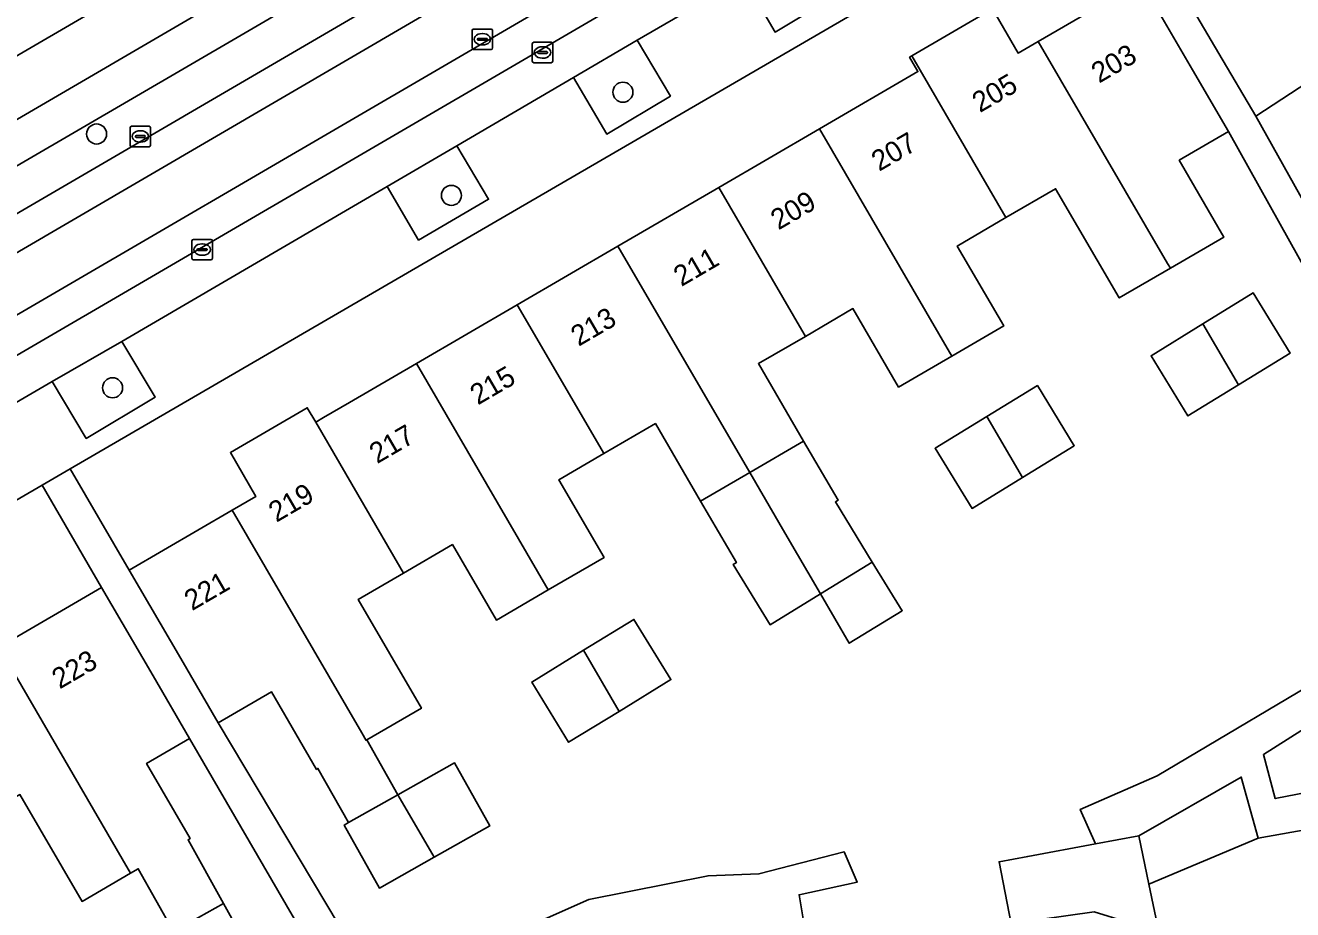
# Model space of a CAD drawing. Extents: x 158352 to 159489, y 383828 to 384603.
# Drawn here: x 158694.5 to 158756.3, y 384098.8 to 384142 of the extents above; entities that cross this region are included whole.
import ezdxf

# ---------------------------------------------------------------- set-up
doc = ezdxf.new("R2010")
doc.units = 0
for name, color, linetype in [('IMGEO_Boom', 7, 'Continuous'), ('IMGEO_Erf', 7, 'Continuous'), ('IMGEO_Groenvoorziening', 7, 'Continuous'), ('IMGEO_Kolk', 7, 'Continuous'), ('IMGEO_Pand', 7, 'Continuous'), ('IMGEO_Pand_nummerreeks', 7, 'Continuous'), ('IMGEO_Parkeervlak_open', 7, 'Continuous'), ('IMGEO_Rijbaan_lokaal_gesloten', 7, 'Continuous'), ('IMGEO_Rijbaan_lokaal_open', 7, 'Continuous'), ('IMGEO_Rioolput', 7, 'Continuous'), ('IMGEO_Voetpad_open', 7, 'Continuous')]:
    doc.layers.add(name, color=color, linetype=linetype)

msp = doc.modelspace()

# ---------------------------------------------------------------- linework, layer by layer
at = {"layer": 'IMGEO_Boom'}
for centre in [(158723.642, 384138.721), (158697.952, 384136.681), (158715.271, 384133.683), (158698.731, 384124.289)]:
    msp.add_circle(centre, 0.489, dxfattribs=at)
at = {"layer": 'IMGEO_Erf'}
for points in [[(158728.317, 384134.065), (158733.235, 384136.93), (158738.044, 384139.731), (158737.635, 384140.432), (158737.742, 384140.494), (158741.679, 384142.788), (158742.934, 384140.632), (158743.915, 384141.203), (158748.936, 384144.128), (158746.068, 384149.06), (158696.667, 384120.326), (158699.543, 384115.387), (158704.565, 384118.312), (158705.726, 384118.988), (158704.48, 384121.126), (158708.237, 384123.314), (158708.648, 384122.608), (158709.034, 384122.833), (158710.296, 384123.568), (158713.565, 384125.472), (158718.482, 384128.337), (158723.4, 384131.201)], [(158749.422, 384125.856), (158751.95, 384127.408), (158754.412, 384128.919), (158756.216, 384125.98), (158753.686, 384124.427), (158751.225, 384122.917)], [(158743.147, 384119.907), (158740.687, 384118.397), (158738.884, 384121.336), (158741.411, 384122.887), (158743.874, 384124.399), (158745.678, 384121.46)], [(158723.454, 384108.49), (158720.994, 384106.98), (158719.191, 384109.919), (158721.718, 384111.47), (158724.181, 384112.982), (158725.985, 384110.043)]]:
    msp.add_lwpolyline(points, close=True, dxfattribs=at)
for points in [[(158757.506, 384139.484), (158754.537, 384137.547), (158766.668, 384115.877)], [(158763.607, 384118.148), (158753.204, 384136.8), (158750.796, 384135.397), (158752.98, 384131.648), (158750.367, 384130.126), (158747.874, 384128.674), (158744.766, 384134.011), (158742.341, 384132.599), (158739.96, 384131.212), (158742.232, 384127.312), (158739.695, 384125.835), (158737.101, 384124.324), (158734.871, 384128.153), (158732.548, 384126.8), (158730.26, 384125.467), (158732.463, 384121.686), (158734.145, 384118.799), (158734.012, 384118.718), (158735.816, 384115.779), (158737.276, 384113.4), (158734.691, 384111.813), (158733.285, 384114.226), (158730.825, 384112.716), (158729.022, 384115.655), (158729.182, 384115.753), (158727.433, 384118.756), (158725.228, 384122.541), (158722.711, 384121.075), (158720.517, 384119.797), (158722.726, 384116.005), (158720.002, 384114.418), (158717.469, 384112.943), (158715.32, 384116.631), (158712.937, 384115.243), (158710.715, 384113.948), (158713.807, 384108.64), (158711.15, 384107.093), (158712.659, 384104.412), (158715.428, 384105.97), (158717.14, 384102.895), (158714.431, 384101.37), (158711.753, 384099.863), (158710.041, 384102.939), (158710.247, 384103.055), (158708.758, 384105.7), (158708.686, 384105.658), (158706.481, 384109.443), (158703.886, 384107.932), (158711.747, 384094.756), (158721.977, 384099.298), (158727.797, 384100.464), (158730.28, 384100.554), (158734.439, 384101.63), (158735.083, 384100.15), (158732.24, 384099.536), (158732.47, 384098.16)], [(158663.516, 384097.136), (158667.47, 384099.439), (158667.836, 384098.811), (158672.701, 384101.645), (158677.609, 384104.504), (158682.517, 384107.363), (158686.152, 384109.48), (158687.223, 384110.104), (158687.424, 384110.221), (158687.039, 384110.883), (158690.908, 384113.137), (158692.142, 384111.017), (158693.182, 384111.623), (158698.194, 384114.542), (158695.294, 384119.527), (158650.651, 384093.56)], [(158773.666, 384118.284), (158754.906, 384106.382), (158755.484, 384104.227), (158775.984, 384108.212)], [(158742.589, 384098.118), (158742.003, 384101.142), (158743.404, 384101.402), (158746.706, 384102.014), (158745.966, 384103.699), (158749.715, 384105.347), (158759.047, 384110.871)], [(158710.112, 384094.03), (158702.49, 384107.167), (158700.391, 384105.945), (158702.524, 384102.282), (158702.415, 384102.219), (158704.147, 384099.109), (158705.859, 384096.034)], [(158701.706, 384097.735), (158699.981, 384100.801), (158699.611, 384100.586), (158697.245, 384099.208), (158694.208, 384104.423), (158691.666, 384102.942), (158689.344, 384101.59), (158691.616, 384097.689)], [(158767.698, 384087.716), (158764.614, 384104.071), (158754.651, 384102.29), (158749.314, 384100.047), (158749.803, 384097.716)]]:
    msp.add_lwpolyline(points, dxfattribs=at)
at = {"layer": 'IMGEO_Groenvoorziening'}
for points in [[(158705.587, 384147.238), (158693.057, 384139.923), (158686.342, 384135.99), (158686.267, 384136.115), (158685.669, 384135.769), (158687.07, 384133.326), (158705.582, 384144.133), (158706.962, 384144.94), (158706.888, 384145.075), (158705.68, 384147.291)], [(158732.669, 384146.127), (158729.543, 384144.295), (158731.072, 384141.657), (158734.16, 384143.528)], [(158721.234, 384139.439), (158722.85, 384136.674), (158725.959, 384138.531), (158724.331, 384141.256)], [(158713.672, 384131.503), (158717.082, 384133.496), (158715.536, 384136.098), (158712.14, 384134.125)], [(158697.447, 384121.82), (158700.802, 384123.825), (158699.176, 384126.548), (158695.787, 384124.599)]]:
    msp.add_lwpolyline(points, close=True, dxfattribs=at)
at = {"layer": 'IMGEO_Kolk'}
for p, q in [((158719.218, 384140.236), (158719.218, 384141.088)), ((158719.293, 384141.162), (158720.145, 384141.162)), ((158719.477, 384140.656), (158719.477, 384140.668)), ((158719.915, 384140.619), (158719.517, 384140.619)), ((158719.52, 384140.705), (158719.918, 384140.705)), ((158719.706, 384140.942), (158719.731, 384140.942)), ((158719.961, 384140.668), (158719.961, 384140.656)), ((158720.219, 384141.088), (158720.219, 384140.236)), ((158720.145, 384140.162), (158719.293, 384140.162)), ((158719.729, 384140.382), (158719.704, 384140.382)), ((158699.586, 384136.135), (158699.586, 384136.987)), ((158699.661, 384137.061), (158700.513, 384137.061)), ((158700.587, 384136.987), (158700.587, 384136.135)), ((158699.845, 384136.555), (158699.845, 384136.567)), ((158700.283, 384136.518), (158699.885, 384136.518)), ((158699.888, 384136.604), (158700.286, 384136.604)), ((158700.097, 384136.281), (158700.072, 384136.281)), ((158700.074, 384136.841), (158700.099, 384136.841)), ((158700.329, 384136.567), (158700.329, 384136.555)), ((158700.513, 384136.061), (158699.661, 384136.061)), ((158702.604, 384130.611), (158702.604, 384131.463)), ((158702.679, 384131.537), (158703.531, 384131.537)), ((158703.092, 384131.317), (158703.117, 384131.317)), ((158703.605, 384131.463), (158703.605, 384130.611)), ((158702.863, 384131.031), (158702.863, 384131.043)), ((158703.301, 384130.994), (158702.903, 384130.994)), ((158702.906, 384131.08), (158703.304, 384131.08)), ((158703.115, 384130.757), (158703.09, 384130.757)), ((158703.347, 384131.043), (158703.347, 384131.031)), ((158703.531, 384130.537), (158702.679, 384130.537))]:
    msp.add_line(p, q, dxfattribs=at)
for points in [[(158719.218, 384140.236), (158719.218, 384141.088)], [(158719.293, 384141.162), (158720.145, 384141.162)], [(158720.219, 384141.088), (158720.219, 384140.236)], [(158720.145, 384140.162), (158719.293, 384140.162)], [(158699.586, 384136.135), (158699.586, 384136.987)], [(158699.661, 384137.061), (158700.513, 384137.061)], [(158700.587, 384136.987), (158700.587, 384136.135)], [(158700.513, 384136.061), (158699.661, 384136.061)], [(158702.604, 384130.611), (158702.604, 384131.463)], [(158702.679, 384131.537), (158703.531, 384131.537)], [(158703.605, 384131.463), (158703.605, 384130.611)], [(158703.531, 384130.537), (158702.679, 384130.537)]]:
    msp.add_lwpolyline(points, dxfattribs=at)
for centre, radius, start, end in [((158719.295, 384141.086), 0.0765, 91.55205, 178.44795), ((158719.295, 384141.086), 0.0765, 91.55205, 178.44795), ((158719.517, 384140.665), 0.0403, 85.87752, 175.75265), ((158719.514, 384140.655), 0.0366, 178.93798, 274.71019), ((158719.918, 384140.662), 0.043, 264.86636, 352.45326), ((158719.922, 384140.667), 0.0386, 1.73085, 96.63898), ((158720.143, 384141.086), 0.0765, 1.55205, 88.44795), ((158720.143, 384141.086), 0.0765, 1.55205, 88.44795), ((158719.295, 384140.238), 0.0765, 181.55205, 268.44795), ((158719.295, 384140.238), 0.0765, 181.55205, 268.44795), ((158720.143, 384140.238), 0.0765, 271.55205, 358.44795), ((158720.143, 384140.238), 0.0765, 271.55205, 358.44795), ((158699.663, 384136.985), 0.0765, 91.55205, 178.44795), ((158699.663, 384136.985), 0.0765, 91.55205, 178.44795), ((158700.511, 384136.985), 0.0765, 1.55205, 88.44795), ((158700.511, 384136.985), 0.0765, 1.55205, 88.44795), ((158699.885, 384136.564), 0.0403, 85.87752, 175.75265), ((158699.882, 384136.554), 0.0366, 178.93798, 274.71019), ((158700.286, 384136.561), 0.043, 264.86636, 352.45326), ((158700.29, 384136.566), 0.0386, 1.73085, 96.63898), ((158699.663, 384136.137), 0.0765, 181.55205, 268.44795), ((158699.663, 384136.137), 0.0765, 181.55205, 268.44795), ((158700.511, 384136.137), 0.0765, 271.55205, 358.44795), ((158700.511, 384136.137), 0.0765, 271.55205, 358.44795), ((158702.681, 384131.461), 0.0765, 91.55205, 178.44795), ((158702.681, 384131.461), 0.0765, 91.55205, 178.44795), ((158703.529, 384131.461), 0.0765, 1.55205, 88.44795), ((158703.529, 384131.461), 0.0765, 1.55205, 88.44795), ((158702.903, 384131.04), 0.0403, 85.87752, 175.75265), ((158702.9, 384131.03), 0.0366, 178.93798, 274.71019), ((158703.304, 384131.037), 0.043, 264.86636, 352.45326), ((158703.308, 384131.042), 0.0386, 1.73085, 96.63898), ((158702.681, 384130.613), 0.0765, 181.55205, 268.44795), ((158702.681, 384130.613), 0.0765, 181.55205, 268.44795), ((158703.529, 384130.613), 0.0765, 271.55205, 358.44795), ((158703.529, 384130.613), 0.0765, 271.55205, 358.44795)]:
    msp.add_arc(centre, radius, start, end, dxfattribs=at)
for centre, major_axis, ratio, start_param, end_param in [((158719.705, 384140.662), (-0.387, 0.002), 0.722429, 4.712389, 7.853982), ((158719.73, 384140.662), (-0.39, 0.002), 0.717154, 1.570796, 4.712389), ((158700.073, 384136.561), (-0.387, 0.002), 0.722429, 4.712389, 7.853982), ((158700.098, 384136.561), (-0.39, 0.002), 0.717154, 1.570796, 4.712389), ((158703.091, 384131.037), (-0.387, 0.002), 0.722429, 4.712389, 7.853982), ((158703.116, 384131.037), (-0.39, 0.002), 0.717154, 1.570796, 4.712389)]:
    msp.add_ellipse(centre, major_axis=major_axis, ratio=ratio, start_param=start_param, end_param=end_param, dxfattribs=at)
at = {"layer": 'IMGEO_Pand'}
msp.add_lwpolyline([(158653.864, 384149.026), (158667.797, 384125.161), (158676.397, 384130.204), (158676.31, 384130.355), (158672.899, 384136.248), (158683.572, 384142.468), (158689.645, 384146.008), (158692.983, 384140.276), (158692.881, 384140.213), (158693.057, 384139.923), (158705.587, 384147.238), (158703.871, 384150.068), (158727.441, 384163.801), (158727.604, 384163.526), (158727.921, 384163.713), (158725.073, 384168.559)], dxfattribs=at)
for points in [[(158762.253, 384137.116), (158762.181, 384137.223), (158754.924, 384148.07), (158750.204, 384144.913), (158752.739, 384140.604), (158754.537, 384137.547), (158757.506, 384139.484), (158760.068, 384135.654)], [(158743.915, 384141.203), (158750.233, 384130.355), (158750.367, 384130.126), (158752.98, 384131.648), (158750.796, 384135.397), (158753.204, 384136.8), (158751.452, 384139.808), (158748.936, 384144.128)], [(158743.915, 384141.203), (158742.934, 384140.632), (158741.679, 384142.788), (158737.742, 384140.494), (158742.341, 384132.599), (158744.766, 384134.011), (158747.874, 384128.674), (158750.367, 384130.126), (158750.233, 384130.355)], [(158733.235, 384136.93), (158739.695, 384125.835), (158742.232, 384127.312), (158739.96, 384131.212), (158742.341, 384132.599), (158737.742, 384140.494), (158737.635, 384140.432), (158738.044, 384139.731)], [(158733.235, 384136.93), (158728.317, 384134.065), (158732.484, 384126.91), (158732.548, 384126.8), (158734.871, 384128.153), (158737.101, 384124.324), (158739.695, 384125.835)], [(158729.833, 384120.154), (158732.463, 384121.686), (158730.26, 384125.467), (158732.548, 384126.8), (158732.484, 384126.91), (158728.317, 384134.065), (158723.4, 384131.201)], [(158718.482, 384128.337), (158722.622, 384121.228), (158722.711, 384121.075), (158725.228, 384122.541), (158727.433, 384118.756), (158729.833, 384120.154), (158723.4, 384131.201)], [(158753.686, 384124.427), (158756.216, 384125.98), (158754.412, 384128.919), (158751.95, 384127.408)], [(158718.482, 384128.337), (158713.565, 384125.472), (158720.002, 384114.418), (158722.726, 384116.005), (158720.517, 384119.797), (158722.711, 384121.075), (158722.622, 384121.228)], [(158753.686, 384124.427), (158751.95, 384127.408), (158749.422, 384125.856), (158751.225, 384122.917)], [(158713.565, 384125.472), (158710.296, 384123.568), (158709.034, 384122.833), (158708.648, 384122.608), (158712.756, 384115.553), (158712.937, 384115.243), (158715.32, 384116.631), (158717.469, 384112.943), (158720.002, 384114.418)], [(158743.147, 384119.907), (158745.678, 384121.46), (158743.874, 384124.399), (158741.411, 384122.887)], [(158712.937, 384115.243), (158712.756, 384115.553), (158708.648, 384122.608), (158708.237, 384123.314), (158704.48, 384121.126), (158705.726, 384118.988), (158704.565, 384118.312), (158710.892, 384107.447), (158711.111, 384107.07), (158711.15, 384107.093), (158713.807, 384108.64), (158710.715, 384113.948)], [(158743.147, 384119.907), (158741.411, 384122.887), (158738.884, 384121.336), (158740.687, 384118.397)], [(158734.012, 384118.718), (158734.145, 384118.799), (158732.463, 384121.686), (158729.833, 384120.154), (158731.549, 384117.206), (158733.285, 384114.226), (158735.816, 384115.779)], [(158731.549, 384117.206), (158729.833, 384120.154), (158727.433, 384118.756), (158729.182, 384115.753), (158729.022, 384115.655), (158730.825, 384112.716), (158733.285, 384114.226)], [(158704.565, 384118.312), (158699.543, 384115.387), (158702.06, 384111.067), (158703.886, 384107.932), (158706.481, 384109.443), (158708.686, 384105.658), (158708.758, 384105.7), (158710.247, 384103.055), (158712.659, 384104.412), (158711.15, 384107.093), (158711.111, 384107.07), (158710.892, 384107.447)], [(158735.816, 384115.779), (158733.285, 384114.226), (158734.691, 384111.813), (158737.276, 384113.4)], [(158700.711, 384110.222), (158698.194, 384114.542), (158693.182, 384111.623), (158699.611, 384100.586), (158699.981, 384100.801), (158701.706, 384097.735), (158704.147, 384099.109), (158702.415, 384102.219), (158702.524, 384102.282), (158700.391, 384105.945), (158702.49, 384107.167)], [(158693.182, 384111.623), (158692.142, 384111.017), (158690.908, 384113.137), (158687.039, 384110.883), (158687.424, 384110.221), (158691.597, 384103.06), (158691.666, 384102.942), (158694.208, 384104.423), (158697.245, 384099.208), (158699.611, 384100.586)], [(158721.718, 384111.47), (158723.454, 384108.49), (158725.985, 384110.043), (158724.181, 384112.982)], [(158721.718, 384111.47), (158719.191, 384109.919), (158720.994, 384106.98), (158723.454, 384108.49)], [(158714.431, 384101.37), (158717.14, 384102.895), (158715.428, 384105.97), (158712.659, 384104.412)], [(158748.819, 384102.406), (158749.314, 384100.047), (158754.651, 384102.29), (158753.83, 384105.283)], [(158712.659, 384104.412), (158710.247, 384103.055), (158710.041, 384102.939), (158711.753, 384099.863), (158714.431, 384101.37)], [(158748.819, 384102.406), (158746.706, 384102.014), (158743.404, 384101.402), (158742.003, 384101.142), (158742.589, 384098.118), (158743.219, 384098.209), (158743.987, 384098.32), (158746.652, 384098.705), (158749.803, 384097.716), (158749.314, 384100.047)], [(158704.147, 384099.109), (158701.706, 384097.735), (158701.379, 384097.551), (158703.151, 384094.509), (158705.859, 384096.034)]]:
    msp.add_lwpolyline(points, close=True, dxfattribs=at)
at = {"layer": 'IMGEO_Parkeervlak_open'}
for points in [[(158734.535, 384156.927), (158732.618, 384157.353), (158732.413, 384157.398), (158732.246, 384157.41), (158732.06, 384157.367), (158715.82, 384147.827), (158672.977, 384122.843), (158669.192, 384120.661), (158669.166, 384120.646)], [(158738.971, 384152.091), (158738.379, 384151.745), (158647.204, 384098.556)], [(158695.787, 384124.599), (158699.176, 384126.548), (158712.14, 384134.125), (158715.536, 384136.098), (158721.234, 384139.439), (158724.331, 384141.256), (158729.543, 384144.295), (158732.669, 384146.127), (158736.874, 384148.589)], [(158667.252, 384117.177), (158667.528, 384117.313), (158716.96, 384146.173)], [(158648.598, 384098.717), (158650.189, 384098.335), (158650.96, 384098.425), (158661.287, 384104.498), (158665.178, 384106.745), (158678.479, 384114.472), (158681.775, 384116.427), (158695.787, 384124.599)]]:
    msp.add_lwpolyline(points, dxfattribs=at)
at = {"layer": 'IMGEO_Rijbaan_lokaal_gesloten'}
for points in [[(158736.245, 384155.536), (158735.439, 384156.968), (158716.96, 384146.173), (158667.528, 384117.313), (158667.252, 384117.177), (158666.707, 384116.86), (158659.63, 384112.744), (158655.57, 384110.383), (158644.427, 384103.877), (158644.032, 384103.668), (158644.915, 384102.204)], [(158738.379, 384151.745), (158737.545, 384153.226), (158646.22, 384099.951), (158647.12, 384098.492), (158647.204, 384098.556)]]:
    msp.add_lwpolyline(points, close=True, dxfattribs=at)
at = {"layer": 'IMGEO_Rijbaan_lokaal_open'}
msp.add_lwpolyline([(158736.245, 384155.536), (158644.915, 384102.204), (158646.22, 384099.951), (158737.545, 384153.226)], close=True, dxfattribs=at)
at = {"layer": 'IMGEO_Rioolput'}
for p, q in [((158716.28, 384140.881), (158716.28, 384141.733)), ((158716.355, 384141.807), (158717.207, 384141.807)), ((158716.539, 384141.301), (158716.539, 384141.313)), ((158716.977, 384141.264), (158716.579, 384141.264)), ((158716.582, 384141.35), (158716.98, 384141.35)), ((158716.768, 384141.587), (158716.793, 384141.587)), ((158717.023, 384141.313), (158717.023, 384141.301)), ((158717.281, 384141.733), (158717.281, 384140.881)), ((158717.207, 384140.807), (158716.355, 384140.807)), ((158716.791, 384141.027), (158716.766, 384141.027))]:
    msp.add_line(p, q, dxfattribs=at)
for points in [[(158716.28, 384140.881), (158716.28, 384141.733)], [(158716.355, 384141.807), (158717.207, 384141.807)], [(158717.281, 384141.733), (158717.281, 384140.881)], [(158717.207, 384140.807), (158716.355, 384140.807)]]:
    msp.add_lwpolyline(points, dxfattribs=at)
for centre, radius, start, end in [((158716.357, 384141.731), 0.0765, 91.55205, 178.44795), ((158716.357, 384141.731), 0.0765, 91.55205, 178.44795), ((158716.579, 384141.31), 0.0403, 85.87752, 175.75265), ((158716.576, 384141.3), 0.0366, 178.93798, 274.71019), ((158716.98, 384141.307), 0.043, 264.86636, 352.45326), ((158716.984, 384141.312), 0.0386, 1.73085, 96.63898), ((158717.205, 384141.731), 0.0765, 1.55205, 88.44795), ((158717.205, 384141.731), 0.0765, 1.55205, 88.44795), ((158716.357, 384140.883), 0.0765, 181.55205, 268.44795), ((158716.357, 384140.883), 0.0765, 181.55205, 268.44795), ((158717.205, 384140.883), 0.0765, 271.55205, 358.44795), ((158717.205, 384140.883), 0.0765, 271.55205, 358.44795)]:
    msp.add_arc(centre, radius, start, end, dxfattribs=at)
for centre, major_axis, ratio, start_param, end_param in [((158716.767, 384141.307), (-0.387, 0.002), 0.722429, 4.712389, 7.853982), ((158716.792, 384141.307), (-0.39, 0.002), 0.717154, 1.570796, 4.712389)]:
    msp.add_ellipse(centre, major_axis=major_axis, ratio=ratio, start_param=start_param, end_param=end_param, dxfattribs=at)
at = {"layer": 'IMGEO_Voetpad_open'}
for points in [[(158743.744, 384163.971), (158741.091, 384164.958), (158709.408, 384146.369), (158706.962, 384144.94), (158705.582, 384144.133), (158687.07, 384133.326), (158684.077, 384131.578), (158669.108, 384122.84), (158667.746, 384122.045), (158663.493, 384119.562), (158658.71, 384116.77), (158649.271, 384111.259), (158644.581, 384108.521), (158640.005, 384105.85), (158634.558, 384102.668), (158635.177, 384101.653), (158631.769, 384099.592), (158631.113, 384100.657), (158615.79, 384091.707)], [(158627.36, 384093.946), (158641.961, 384102.46), (158644.032, 384103.668), (158644.427, 384103.877), (158655.57, 384110.383), (158659.63, 384112.744), (158659.081, 384113.701), (158666.171, 384117.809), (158665.635, 384118.76), (158669.04, 384120.74), (158669.192, 384120.661), (158672.977, 384122.843), (158715.82, 384147.827), (158732.06, 384157.367), (158732.246, 384157.41), (158732.413, 384157.398), (158732.618, 384157.353), (158734.535, 384156.927)], [(158766.668, 384115.877), (158754.537, 384137.547), (158752.739, 384140.604), (158750.204, 384144.913), (158747.356, 384149.809), (158746.068, 384149.06), (158748.936, 384144.128), (158751.452, 384139.808), (158753.204, 384136.8), (158763.607, 384118.148)], [(158643.313, 384090.537), (158643.898, 384089.569), (158650.651, 384093.56), (158695.294, 384119.527), (158696.667, 384120.326), (158746.068, 384149.06)], [(158736.874, 384148.589), (158732.669, 384146.127), (158734.16, 384143.528), (158731.072, 384141.657), (158729.543, 384144.295), (158724.331, 384141.256), (158725.959, 384138.531), (158722.85, 384136.674), (158721.234, 384139.439), (158715.536, 384136.098), (158717.082, 384133.496), (158713.672, 384131.503), (158712.14, 384134.125), (158699.176, 384126.548), (158700.802, 384123.825), (158697.447, 384121.82), (158695.787, 384124.599), (158681.775, 384116.427)], [(158732.47, 384098.16), (158732.24, 384099.536), (158735.083, 384100.15), (158734.439, 384101.63), (158730.28, 384100.554), (158727.797, 384100.464), (158721.977, 384099.298), (158711.747, 384094.756), (158703.886, 384107.932), (158702.06, 384111.067), (158699.543, 384115.387), (158696.667, 384120.326), (158695.294, 384119.527), (158698.194, 384114.542), (158700.711, 384110.222), (158702.49, 384107.167), (158710.112, 384094.03)], [(158775.984, 384108.212), (158755.484, 384104.227), (158754.906, 384106.382), (158773.666, 384118.284)], [(158759.047, 384110.871), (158749.715, 384105.347), (158745.966, 384103.699), (158746.706, 384102.014), (158748.819, 384102.406), (158753.83, 384105.283), (158754.651, 384102.29), (158764.614, 384104.071)]]:
    msp.add_lwpolyline(points, dxfattribs=at)

# ---------------------------------------------------------------- texts
at = {"layer": 'IMGEO_Pand_nummerreeks'}
for s, rotation, p in [('203', 30.23656, (158746.887, 384139.138)), ('205', 30.22032, (158741.069, 384137.698)), ('207', 30.22032, (158736.152, 384134.833)), ('209', 30.22032, (158731.235, 384131.969)), ('211', 30.22032, (158726.496, 384129.208)), ('213', 30.22032, (158721.48, 384126.287)), ('215', 30.22032, (158716.562, 384123.423)), ('217', 30.21779, (158711.644, 384120.558)), ('219', 30.21779, (158706.727, 384117.694)), ('221', 30.21779, (158702.61, 384113.378)), ('223', 30.22352, (158696.149, 384109.554))]:
    msp.add_text(s, height=1, rotation=rotation, dxfattribs=at).set_placement(p)

doc.saveas('drawing.dxf')
